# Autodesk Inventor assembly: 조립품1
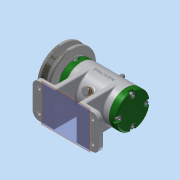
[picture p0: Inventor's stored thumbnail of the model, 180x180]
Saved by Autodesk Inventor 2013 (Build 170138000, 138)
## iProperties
Created: 2017-02
Part Number: 조립품1
Document SubType Name: Assembly
Designer: Administrator
Author: Administrator
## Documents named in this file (16)
- C:\Users\Administrator\Desktop\470208V1004\조립품1.iam
- C:\Users\Administrator\Desktop\470208V1004\V벨트풀리.ipt
- C:\Users\Administrator\Desktop\470208V1004\너트 M 8.ipt
- C:\Users\Administrator\Desktop\470208V1004\스프링와셔 8.ipt
- C:\Users\Administrator\Desktop\470208V1004\와셔 8x17.ipt
- C:\Users\Administrator\Desktop\470208V1004\키 3 x 3 x 12.ipt
- C:\Users\Administrator\Desktop\470208V1004\본체.ipt
- C:\Users\Administrator\Desktop\470208V1004\축.ipt
- C:\Users\Administrator\Desktop\470208V1004\베어링 15 x 32 x 9.ipt
- C:\Users\Administrator\Desktop\470208V1004\앞커버.ipt
- C:\Users\Administrator\Desktop\470208V1004\오일 실 15 25 7.ipt
- C:\Users\Administrator\Desktop\470208V1004\뒤커버.ipt
- C:\Users\Administrator\Desktop\470208V1004\볼트 M4 x 12.ipt
- C:\Users\Administrator\Desktop\470208V1004\니플 M 6 x 0.75.ipt
- C:\Users\Administrator\Desktop\470208V1004\볼트 M 6 x 8.ipt
- C:\Users\Administrator\Desktop\470208V1004\와셔 6x11.5.ipt
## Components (11 placed, 3 different names)
1. V벨트풀리:1
2. KS B 2023 6002 - 15 x 32 x 9:1
3. KS B 2023 6002 - 15 x 32 x 9:2
4. ISO 4762 M4 x 12:1
5. ISO 4762 M4 x 12:2
6. ISO 4762 M4 x 12:3
7. ISO 4762 M4 x 12:4
8. ISO 4762 M4 x 12:5
9. ISO 4762 M4 x 12:6
10. ISO 4762 M4 x 12:7
11. ISO 4762 M4 x 12:8
